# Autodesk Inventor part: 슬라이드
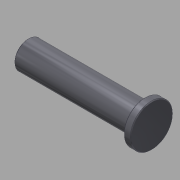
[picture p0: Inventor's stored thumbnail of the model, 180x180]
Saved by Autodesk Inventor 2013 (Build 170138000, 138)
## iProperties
Created: 2015-10
Part Number: 슬라이드
Document SubType Name: Modeling
Designer: mdu
Density: 7.86 g/cm^3
Material: 강철, 연강
Mass: 1603.27 g
Surface Area: 269.019 cm^2
Volume: 203.978 cm^3
Author: mdu
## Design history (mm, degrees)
sketch "스케치1"
  geometry: L1 (-75, 162)-(-75, 58) reference; L2 (-148, 110)-(22, 110); L3 (-148, 110)-(-148, 129); L4 (-148, 129)-(12, 129); L5 (12, 129)-(12, 139); L6 (12, 139)-(22, 139); L7 (22, 139)-(22, 110); 2 further points
  constraints: 12 end point, 3 parallel, 3 perpendicular, 1 midpoint, 1 point on line
  dimensions: "d0" = 58 diameter of L6 L2; "d1" = 38 diameter of L4 L2; "d2" = 10 distance of L5.end L6.end; "d3" = 170 distance of L2.start L2.end; "d4" = 73 distance between parallel lines of L3 L1
revolve "회전1" sketch "스케치1" stored, may be unused: angle "d5" = 90 deg
hole "구멍1" diameter "d11" = 13.376; stored, may be unused: countersink angle "d15" = 90 deg, drill point angle "d17" = 118 deg; dims "d9" = 10, "d10" = 10, "d12" = 22, "d13" = 4, "d14" = 2, "d16" = 25
chamfer "모따기1" distance "d6" = 1; stored, may be unused: second distance "d7" = 2, angle "d8" = 45 deg
node "솔리드1"
node "참조1"
